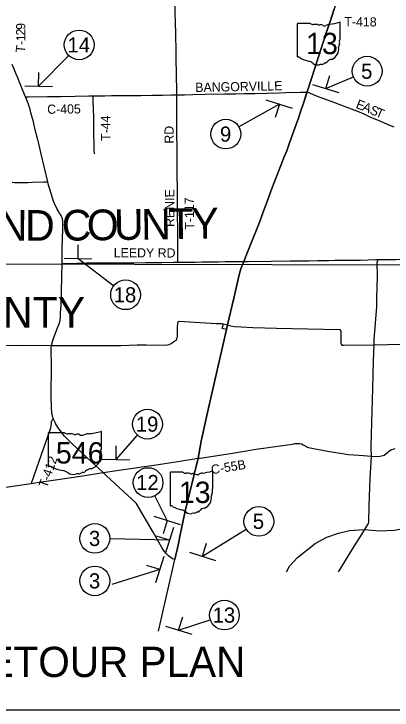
# Model space of a CAD drawing. Extents: x 40529 to 41139, y 15164 to 15584.
# Drawn here: x 40618.2 to 40688.2, y 15164.3 to 15293.1 of the extents above; entities that cross this region are included whole.
import ezdxf

# ---------------------------------------------------------------- set-up
doc = ezdxf.new("R2010")
doc.units = 0
for name, color, linetype in [('Default', 7, 'Continuous'), ('GM_X_County_Road', 7, 'Continuous'), ('GM_X_County_Road_Text', 7, 'Continuous'), ('GM_X_County_Text', 7, 'Continuous'), ('GM_X_Rail_Line', 7, 'Continuous'), ('GM_X_State_Location', 7, 'Continuous'), ('GM_X_State_Route', 7, 'Continuous'), ('GM_X_State_Shield', 7, 'Continuous'), ('GM_X_Township_Road', 7, 'Continuous'), ('GM_X_Township_Road_Text', 7, 'Continuous'), ('SC_Scratch1', 7, 'Continuous'), ('SH_Cut_Line', 7, 'Continuous'), ('SH_Data', 7, 'Continuous'), ('SH_Text', 7, 'Continuous')]:
    doc.layers.add(name, color=color, linetype=linetype)

msp = doc.modelspace()

# ---------------------------------------------------------------- linework, layer by layer
at = {"layer": 'Default'}
for p, q in [((40622.79, 15279.77), (40622.83, 15282.32)), ((40675.89, 15279.34), (40676.65, 15281.77)), ((40620.24, 15279.81), (40625.34, 15279.73)), ((40673.46, 15280.1), (40678.32, 15278.58)), ((40669.76, 15275.65), (40664.9, 15277.18)), ((40667.33, 15276.42), (40666.57, 15273.98)), ((40630.09, 15247.89), (40630.13, 15250.44)), ((40627.54, 15247.93), (40632.64, 15247.85)), ((40637.12, 15210.69), (40637.16, 15213.23)), ((40634.57, 15210.73), (40639.67, 15210.64)), ((40649.03, 15198.61), (40644.17, 15200.13)), ((40646.6, 15199.37), (40645.84, 15196.94)), ((40646.27, 15193.32), (40647.8, 15198.18)), ((40647.03, 15195.75), (40644.6, 15196.51)), ((40653.11, 15192.78), (40653.87, 15195.21)), ((40650.68, 15193.54), (40655.54, 15192.02)), ((40644.47, 15187.91), (40646, 15192.77)), ((40645.23, 15190.34), (40642.8, 15191.1)), ((40648.67, 15179.11), (40649.44, 15181.54)), ((40646.24, 15179.87), (40651.11, 15178.34))]:
    msp.add_line(p, q, dxfattribs=at)
at = {"layer": 'GM_X_County_Road'}
for points in [[(40648.34, 15278.15), (40648.5, 15278.15), (40649.8, 15278.2), (40651.29, 15278.24), (40653.62, 15278.29), (40657.16, 15278.33), (40659.2, 15278.37), (40660.88, 15278.39), (40662, 15278.43), (40662.83, 15278.45), (40667.3, 15278.55), (40668.51, 15278.59), (40671.21, 15278.67), (40672.24, 15278.69), (40672.42, 15278.68)], [(40672.42, 15278.68), (40672.51, 15278.67), (40672.6, 15278.65), (40672.77, 15278.59), (40673.72, 15278.2), (40674.83, 15277.76), (40677.01, 15276.93), (40681.1, 15275.37), (40682.06, 15275), (40682.91, 15274.63), (40684.19, 15274.07), (40685.57, 15273.49), (40687.71, 15272.58), (40688.49, 15272.27)], [(40620.37, 15277.82), (40620.56, 15277.82), (40620.84, 15277.83), (40624.44, 15277.87), (40625.82, 15277.86), (40626.94, 15277.86), (40629.55, 15277.9), (40632.06, 15277.96), (40632.81, 15277.97), (40632.92, 15277.98)], [(40632.92, 15277.98), (40635.04, 15278.01), (40636.25, 15278.02), (40638.29, 15278.05), (40641.72, 15278.07), (40643.85, 15278.11), (40645.71, 15278.13), (40647.39, 15278.15), (40648.34, 15278.15)], [(40661.25, 15212.3), (40662.59, 15212.51), (40665.65, 15212.98), (40669.74, 15213.54), (40670.2, 15213.64), (40670.73, 15213.67), (40671.12, 15213.65), (40671.42, 15213.56), (40671.69, 15213.43), (40672.2, 15213.16), (40672.42, 15213.04), (40672.73, 15212.9), (40673.02, 15212.83), (40673.61, 15212.7), (40676.98, 15212.1), (40678.65, 15211.83), (40679.29, 15211.73), (40680.02, 15211.64), (40681.12, 15211.52), (40682.89, 15211.41), (40684.38, 15211.33), (40685.64, 15211.24), (40686.22, 15211.34), (40686.71, 15211.49), (40687.35, 15212.02), (40687.67, 15212.27), (40687.94, 15212.45), (40688.76, 15212.74)], [(40652.31, 15210.93), (40652.65, 15210.95), (40653.09, 15210.99), (40658.63, 15211.87), (40661.25, 15212.3)]]:
    msp.add_lwpolyline(points, dxfattribs=at)
at = {"layer": 'GM_X_Rail_Line'}
msp.add_lwpolyline([(40668.64, 15189.89), (40669.2, 15190.96), (40670.65, 15192.58), (40673.94, 15195.16), (40676.07, 15196.33), (40678.25, 15197.05), (40680.29, 15197.55), (40682.99, 15197.72), (40685.84, 15197.5), (40688.61, 15197.62), (40690.98, 15198.06), (40693.48, 15198.84), (40697.28, 15200.43), (40705.39, 15204.07), (40707.45, 15205.06), (40708.87, 15205.81), (40710.96, 15207.11), (40717.07, 15211.94), (40723.79, 15217.72), (40727.32, 15220.6), (40729.54, 15222.69), (40732.21, 15225.65), (40737.65, 15232.65)], dxfattribs=at)
at = {"layer": 'GM_X_State_Route'}
msp.add_line((40644.96, 15178.94), (40647.96, 15192.15), dxfattribs=at)
for points in [[(40660.77, 15247.32), (40660.89, 15247.63), (40661.19, 15248.42), (40661.82, 15249.97), (40663.68, 15254.75), (40664.2, 15256.14), (40664.9, 15257.97), (40665.38, 15259.28), (40665.7, 15260.16), (40666.26, 15261.64), (40666.95, 15263.47), (40667.61, 15265.11), (40668.23, 15266.67), (40668.67, 15267.8), (40669.22, 15269.29), (40670.01, 15271.48), (40670.85, 15273.85), (40671.24, 15275), (40671.82, 15276.82), (40672.42, 15278.68), (40672.57, 15279.08), (40674.5, 15285.02), (40675.94, 15289.44), (40676.69, 15291.75), (40677.45, 15294.1)], [(40627.16, 15246.98), (40627.16, 15247.21), (40627.18, 15249.8), (40627.26, 15253.34), (40627.28, 15254.38), (40627.27, 15254.66), (40627.26, 15254.86), (40627.24, 15255.04), (40627.2, 15255.24), (40627.14, 15255.44), (40627.05, 15255.65), (40626.95, 15255.83), (40626.67, 15256.28), (40626.41, 15256.71), (40626.23, 15257.04), (40626.15, 15257.2), (40625.94, 15257.62), (40625.75, 15258.04), (40625.57, 15258.47), (40625.43, 15258.89), (40624.93, 15260.51), (40624.63, 15261.48), (40624.5, 15262), (40624.48, 15262.09), (40623.81, 15264.92), (40623.23, 15267.47), (40622.82, 15269.18), (40622.7, 15269.64), (40622.66, 15269.81), (40622.6, 15270.07), (40622.18, 15271.72), (40621.83, 15273.16), (40621.38, 15274.87), (40621.22, 15275.49), (40620.99, 15276.2), (40620.84, 15276.64), (40620.37, 15277.82), (40619.91, 15278.98), (40619.39, 15280.2), (40618.94, 15281.3), (40618.66, 15282), (40618.27, 15282.93), (40617.93, 15283.79)], [(40625.16, 15221.13), (40625.15, 15221.6), (40625.13, 15222.3), (40625.13, 15222.45), (40625.12, 15222.94), (40625.12, 15223.42), (40625.21, 15227.09), (40625.2, 15228.84), (40625.15, 15230.42), (40625.15, 15231.49), (40625.19, 15231.79), (40625.28, 15232.19), (40625.4, 15232.55), (40625.64, 15233.25), (40626.31, 15235.03), (40626.61, 15235.82), (40626.76, 15236.39), (40626.84, 15237.11), (40626.87, 15237.81), (40626.95, 15239.27), (40627.16, 15246.98)], [(40652.31, 15210.93), (40652.89, 15214.07), (40654.18, 15219.95), (40657.52, 15234.76), (40657.73, 15235.58), (40658.88, 15240.56), (40659.86, 15244.86), (40660.05, 15245.55), (40660.19, 15245.98), (40660.77, 15247.32)], [(40626.57, 15216.35), (40626.38, 15216.64), (40626.13, 15217.01), (40625.93, 15217.35), (40625.84, 15217.53), (40625.71, 15217.79), (40625.56, 15218.13), (40625.45, 15218.44), (40625.36, 15218.79), (40625.3, 15219.08), (40625.27, 15219.28), (40625.24, 15219.45), (40625.22, 15219.68), (40625.2, 15219.95), (40625.18, 15220.24), (40625.19, 15220.44), (40625.17, 15220.91), (40625.16, 15221.13)], [(40645.6, 15194.4), (40643.96, 15197.21), (40640.86, 15202.61), (40635.37, 15207.67), (40634.72, 15208.27), (40632.5, 15210.31), (40629.03, 15213.58), (40627.93, 15214.65), (40627.6, 15215), (40626.98, 15215.79), (40626.65, 15216.22), (40626.57, 15216.35)], [(40649.47, 15199.11), (40649.9, 15201.14), (40652.31, 15210.93)], [(40647.96, 15192.15), (40648.58, 15194.83), (40649.03, 15197.04), (40649.47, 15199.11)], [(40647.96, 15192.15), (40647.57, 15192.3), (40646.82, 15192.85), (40646.37, 15193.28), (40645.89, 15193.91), (40645.6, 15194.4)]]:
    msp.add_lwpolyline(points, dxfattribs=at)
at = {"layer": 'GM_X_State_Shield'}
for p, q in [((40670.64, 15291.28), (40670.64, 15285.28)), ((40673.03, 15291.39), (40670.71, 15291.39)), ((40678.55, 15288.4), (40678.55, 15291.54)), ((40678.55, 15288.4), (40678.55, 15288.4)), ((40624.57, 15215.52), (40624.57, 15209.51)), ((40627.56, 15215.62), (40624.67, 15215.62)), ((40634.46, 15212.63), (40634.46, 15215.77)), ((40634.45, 15212.63), (40634.46, 15212.63)), ((40647.11, 15208.22), (40647.11, 15202.21)), ((40649.5, 15208.32), (40647.19, 15208.32)), ((40655.02, 15205.33), (40655.02, 15208.47)), ((40655.02, 15205.33), (40655.02, 15205.33))]:
    msp.add_line(p, q, dxfattribs=at)
for centre, radius, start, end in [((40670.73, 15291.3), 0.0916, 98.1301, 188.1301), ((40673.58, 15292.08), 0.889, 231.6195, 271.1119), ((40673.88, 15288.02), 3.19, 80.4867, 94.9883), ((40676.8, 15289.55), 1.69, 97.3462, 120.7689), ((40675.73, 15299.57), 8.39, 275.8445, 288.9065), ((40678.46, 15291.55), 0.0881, 351.8621, 97.738), ((40674.6, 15291.33), 0.256, 219.7921, 297.1024), ((40674.98, 15290.63), 0.533, 54.4667, 119.1411), ((40675.67, 15291.59), 0.641, 233.8562, 294.8282), ((40678.86, 15287.08), 0.595, 136.8065, 186.9296), ((40678.53, 15288.16), 0.136, 107.944, 210.337), ((40677.66, 15287.77), 0.818, 340.033, 23.6496), ((40678.45, 15288.38), 0.0942, 289.6038, 7.7341), ((40676.2, 15286.68), 2.1, 292.3089, 8.9858), ((40670.73, 15285.27), 0.0925, 171.9584, 258.3066), ((40670.74, 15285.88), 0.706, 267.339, 280.6039), ((40670.89, 15284.93), 0.254, 29.7484, 93.2717), ((40674.1, 15290.33), 6.06, 240.4129, 257.1985), ((40672.29, 15282.58), 1.9, 47.1842, 75.836), ((40674.34, 15284.9), 1.2, 230.7004, 286.2918), ((40675.04, 15282.83), 0.988, 85.6951, 111.2099), ((40675.13, 15284.45), 0.641, 268.777, 315.5493), ((40675.7, 15283.87), 0.18, 65.7517, 132.6484), ((40675.63, 15284.7), 0.678, 282.8732, 323.2771), ((40677.08, 15283.59), 1.15, 94.4031, 142.5768), ((40647.2, 15208.23), 0.0916, 98.1301, 188.1301), ((40650.06, 15209.02), 0.889, 231.6195, 271.1119), ((40650.35, 15204.95), 3.19, 80.4867, 94.9883), ((40651.08, 15208.26), 0.256, 219.7921, 297.1024), ((40651.45, 15207.57), 0.533, 54.4667, 119.1411), ((40652.14, 15208.52), 0.641, 233.8562, 294.8282), ((40653.27, 15206.49), 1.69, 97.3462, 120.7689), ((40652.2, 15216.51), 8.39, 275.8445, 288.9065), ((40654.93, 15208.48), 0.0881, 351.8621, 97.738), ((40655, 15205.1), 0.136, 107.944, 210.337), ((40654.13, 15204.7), 0.818, 340.033, 23.6496), ((40654.93, 15205.32), 0.0942, 289.6038, 7.7341), ((40652.67, 15203.62), 2.1, 292.3089, 8.9858), ((40655.34, 15204.02), 0.595, 136.8065, 186.9296), ((40647.2, 15202.2), 0.0925, 171.9584, 258.3066), ((40647.22, 15202.82), 0.706, 267.339, 280.6039), ((40647.36, 15201.87), 0.254, 29.7484, 93.2717), ((40650.57, 15207.26), 6.06, 240.4129, 257.1985), ((40648.77, 15199.52), 1.9, 47.1842, 75.836), ((40652.1, 15201.63), 0.678, 282.8732, 323.2771), ((40653.56, 15200.53), 1.15, 94.4031, 142.5768), ((40650.82, 15201.84), 1.2, 230.7004, 286.2918), ((40651.51, 15199.76), 0.988, 85.6951, 111.2099), ((40651.6, 15201.39), 0.641, 268.777, 315.5493), ((40652.18, 15200.81), 0.18, 65.7517, 132.6484)]:
    msp.add_arc(centre, radius, start, end, dxfattribs=at)
for centre, major_axis, start_param, end_param in [((40624.68, 15215.53), (0.115, 0), 1.712693, 3.28349), ((40628.25, 15216.32), (1.11, 0), 4.042523, 4.731795), ((40628.62, 15212.25), (3.99, 0), 1.404758, 1.657858), ((40629.52, 15215.56), (0.321, 0), 3.836095, 5.185415), ((40630, 15214.87), (0.666, 0), 0.950623, 2.079405), ((40630.86, 15215.82), (0.802, 0), 4.081561, 5.145723), ((40632.27, 15213.79), (2.11, 0), 1.699011, 2.107814), ((40630.93, 15223.81), (10.49, 0), 4.814394, 5.042369), ((40634.35, 15215.78), (0.11, 0), 6.141152, 7.989035), ((40634.34, 15212.62), (0.118, 0), 5.05454, 6.418171), ((40634.85, 15211.32), (0.744, 0), 2.387724, 3.262537), ((40634.43, 15212.4), (0.17, 0), 1.883978, 3.671073), ((40633.35, 15212), (1.02, 0), 5.934695, 6.695948), ((40631.52, 15210.92), (2.62, 0), 5.101752, 6.440018), ((40624.68, 15209.5), (0.116, 0), 3.00124, 4.508301), ((40624.7, 15210.12), (0.882, 0), 4.665946, 4.897461), ((40624.88, 15209.17), (0.318, 0), 0.519207, 1.627899), ((40628.9, 15214.56), (7.57, 0), 4.195997, 4.488961), ((40632.63, 15207.83), (1.44, 0), 1.647645, 2.488434), ((40626.64, 15206.82), (2.37, 0), 0.823519, 1.323587), ((40629.2, 15209.14), (1.5, 0), 4.026481, 4.996735), ((40630.07, 15207.06), (1.24, 0), 1.495662, 1.94098), ((40630.18, 15208.69), (0.801, 0), 4.691044, 5.507374), ((40630.9, 15208.11), (0.226, 0), 1.147584, 2.315152), ((40630.81, 15208.93), (0.847, 0), 4.937069, 5.64225)]:
    msp.add_ellipse(centre, major_axis=major_axis, ratio=0.8, start_param=start_param, end_param=end_param, dxfattribs=at)
at = {"layer": 'GM_X_Township_Road'}
for p, q in [((40656.77, 15234.92), (40656.97, 15235.8)), ((40657.52, 15234.76), (40656.77, 15234.92)), ((40648.52, 15210.32), (40652.31, 15210.93))]:
    msp.add_line(p, q, dxfattribs=at)
for points in [[(40648.34, 15278.15), (40648.33, 15279.06), (40648.3, 15281.66), (40648.25, 15285.2), (40648.21, 15286.87), (40648.18, 15288.73), (40648.16, 15289.66), (40648.13, 15291.34), (40648.08, 15293.67), (40648.04, 15295.52), (40647.98, 15298.33), (40647.97, 15300.28), (40647.95, 15302.23), (40647.88, 15305.57), (40647.89, 15306.52), (40647.9, 15307.91), (40647.87, 15308.93), (40647.86, 15310.14), (40647.85, 15310.43), (40647.85, 15310.89), (40647.86, 15312.19), (40647.84, 15313.87), (40647.84, 15314.8), (40647.84, 15315.41)], [(40633.2, 15267.26), (40633.15, 15267.34), (40633.13, 15267.43), (40633.1, 15267.8), (40633.08, 15268.27), (40633.06, 15269.75), (40633.04, 15270.22), (40633.02, 15271.14), (40633.01, 15272.07), (40632.99, 15274.4), (40632.98, 15275.23), (40632.95, 15275.97), (40632.92, 15276.62), (40632.92, 15277.36), (40632.92, 15277.83), (40632.92, 15277.98)], [(40648.54, 15247.2), (40648.54, 15247.43), (40648.54, 15248.27), (40648.56, 15250.04), (40648.54, 15252.37), (40648.53, 15252.92), (40648.53, 15253.67), (40648.51, 15255.53), (40648.49, 15257.77), (40648.48, 15258.14), (40648.48, 15258.7), (40648.48, 15259.72), (40648.47, 15260.65), (40648.44, 15263.45), (40648.43, 15264.94), (40648.43, 15266.8), (40648.41, 15268.29), (40648.4, 15268.85), (40648.38, 15270.43), (40648.37, 15271.82), (40648.36, 15272.38), (40648.36, 15273.58), (40648.37, 15274.42), (40648.38, 15276.47), (40648.34, 15278.05), (40648.34, 15278.15)], [(40617.94, 15261.98), (40617.97, 15261.98), (40618.35, 15261.96), (40619.01, 15261.95), (40619.84, 15261.96), (40620.86, 15261.97), (40621.7, 15261.99), (40623.74, 15262.05), (40624.26, 15262.08), (40624.48, 15262.09)], [(40660.77, 15247.32), (40661.59, 15247.32), (40665.77, 15247.37), (40669.3, 15247.43), (40672.75, 15247.48), (40674.42, 15247.5), (40676.47, 15247.53), (40677.59, 15247.55), (40678.23, 15247.56), (40678.95, 15247.57), (40679.86, 15247.57), (40680.66, 15247.59), (40682.33, 15247.6), (40685.08, 15247.67)], [(40684.29, 15213.1), (40684.41, 15217.54), (40684.59, 15223.84), (40684.72, 15228.94), (40684.82, 15231.93), (40684.88, 15232.88), (40685.09, 15235.93), (40685.34, 15239), (40685.36, 15239.72), (40685.37, 15240.52), (40685.47, 15244.6), (40685.42, 15247.21), (40685.51, 15247.5), (40685.74, 15247.69)], [(40685.08, 15247.67), (40685.49, 15247.68), (40685.74, 15247.69)], [(40685.74, 15247.69), (40686.33, 15247.69), (40688.94, 15247.7), (40691.17, 15247.73), (40695.36, 15247.83), (40696.01, 15247.84), (40696.2, 15247.85), (40697.31, 15247.84), (40698.71, 15247.87), (40700.57, 15247.9), (40701.88, 15247.92), (40704.11, 15247.96), (40705.42, 15247.99), (40706.62, 15248.01), (40708.95, 15248.07), (40709.04, 15248.07)], [(40627.16, 15246.98), (40627.34, 15246.98), (40627.62, 15246.97), (40628.07, 15246.98), (40631.63, 15247.06), (40633.77, 15247.06), (40636.46, 15247.08), (40637.48, 15247.08), (40638.6, 15247.08), (40639.16, 15247.09), (40640.38, 15247.11), (40642.6, 15247.12), (40644, 15247.14), (40645.02, 15247.16), (40645.3, 15247.17), (40645.58, 15247.17), (40647.72, 15247.18), (40648.54, 15247.2)], [(40648.54, 15247.2), (40648.65, 15247.2), (40649.77, 15247.22), (40649.95, 15247.22), (40650.42, 15247.22), (40651.72, 15247.23), (40653.02, 15247.25), (40653.95, 15247.26), (40656, 15247.28), (40657.31, 15247.3), (40658.52, 15247.32), (40659.91, 15247.33), (40660.75, 15247.32), (40660.77, 15247.32)], [(40648.33, 15232.91), (40648.39, 15233.11), (40648.47, 15233.39), (40648.49, 15234.98), (40648.54, 15236.03), (40648.61, 15236.13)], [(40648.61, 15236.13), (40648.62, 15236.15), (40648.82, 15236.26), (40651.7, 15236.08), (40655.63, 15235.86), (40656.76, 15235.84), (40656.97, 15235.8), (40657.73, 15235.58)], [(40657.73, 15235.58), (40658.09, 15235.48), (40658.37, 15235.4), (40659.03, 15235.3), (40660.25, 15235.25), (40662.39, 15235.1), (40666.82, 15235.02), (40678.39, 15234.76), (40678.57, 15234.72), (40678.64, 15234.65), (40678.7, 15234.45), (40678.69, 15232.24), (40678.75, 15232.01), (40678.87, 15231.87), (40679.18, 15231.82), (40684.82, 15231.93)], [(40625.19, 15231.79), (40626.61, 15231.79), (40630.92, 15231.79), (40638.02, 15231.81), (40641.02, 15231.88), (40642.68, 15231.92), (40646.06, 15231.86), (40646.62, 15231.89), (40646.95, 15231.97), (40647.33, 15232.18), (40648.02, 15232.62), (40648.33, 15232.91)], [(40684.82, 15231.93), (40687.33, 15231.95), (40694.11, 15232.1), (40702.2, 15232.34), (40711.73, 15232.62)], [(40584.24, 15231.84), (40586.47, 15231.86), (40590.24, 15231.86), (40596.86, 15231.81), (40598.4, 15231.81), (40605.68, 15231.86), (40610.27, 15231.79), (40618.87, 15231.82), (40625.19, 15231.79)], [(40625.56, 15218.13), (40625.33, 15217.95), (40625.26, 15217.87), (40625.19, 15217.77), (40625.15, 15217.67), (40625.13, 15217.57), (40625.11, 15217.36), (40625, 15216.62), (40624.91, 15216.27), (40624.79, 15215.9), (40623.27, 15211.58), (40621.4, 15206.26)], [(40678.25, 15189.89), (40678.66, 15190.6), (40680.9, 15194.21), (40682.62, 15196.95), (40683.66, 15198.65), (40683.78, 15198.83), (40683.85, 15199.1), (40683.93, 15202.16), (40684.08, 15207.17), (40684.38, 15211.33), (40684.28, 15212.84), (40684.28, 15212.93), (40684.29, 15213.1)], [(40634.72, 15208.27), (40639.8, 15209.03), (40644.52, 15209.69), (40648.52, 15210.32)], [(40621.4, 15206.26), (40622.93, 15206.49), (40626.35, 15206.97), (40630.99, 15207.69), (40634.72, 15208.27)], [(40608.09, 15204.34), (40609.72, 15204.56), (40613.29, 15205.1), (40617.6, 15205.68), (40621.4, 15206.26)]]:
    msp.add_lwpolyline(points, dxfattribs=at)
at = {"layer": 'SC_Scratch1'}
msp.add_lwpolyline([(40528.65, 15584.31), (41138.65, 15584.31), (41138.65, 15164.31), (40528.65, 15164.31)], close=True, dxfattribs=at)
at = {"layer": 'SH_Cut_Line'}
msp.add_line((40533.65, 15247.13), (40737.65, 15246.6), dxfattribs=at)
at = {"layer": 'SH_Data'}
for p, q in [((40622.79, 15279.77), (40628.37, 15285.45)), ((40675.89, 15279.34), (40681.02, 15281.49)), ((40667.33, 15276.42), (40659.82, 15272.24)), ((40630.09, 15247.89), (40636.69, 15242.84)), ((40637.12, 15210.69), (40641.11, 15215.17)), ((40646.6, 15199.37), (40644.28, 15203.97)), ((40653.11, 15192.78), (40661.19, 15197.79)), ((40647.03, 15195.75), (40635.95, 15196.02)), ((40645.23, 15190.34), (40636.33, 15187.56)), ((40648.67, 15179.11), (40654.54, 15181.03))]:
    msp.add_line(p, q, dxfattribs=at)
msp.add_lwpolyline([(40677.67, 15294.78), (40676.69, 15291.75), (40675.94, 15289.44), (40674.5, 15285.02), (40672.57, 15279.08), (40671.82, 15276.82), (40671.24, 15275), (40670.85, 15273.85), (40670.01, 15271.48), (40669.22, 15269.29), (40668.67, 15267.8), (40668.23, 15266.67), (40667.61, 15265.11), (40666.26, 15261.64), (40665.7, 15260.16), (40664.9, 15257.97), (40664.2, 15256.14), (40663.68, 15254.75), (40661.82, 15249.97), (40661.19, 15248.42), (40660.89, 15247.63), (40660.77, 15247.32), (40660.19, 15245.98), (40659.86, 15244.86), (40658.88, 15240.56), (40657.73, 15235.58), (40657.52, 15234.76), (40654.18, 15219.95), (40652.89, 15214.07), (40652.31, 15210.93), (40649.9, 15201.14), (40649.47, 15199.11), (40649.03, 15197.04), (40648.58, 15194.83), (40647.96, 15192.15)], dxfattribs=at)
at = {"layer": 'SH_Text'}
for centre in [(40630.3, 15287.41), (40683.56, 15282.55), (40657.42, 15270.91), (40638.88, 15241.17), (40642.94, 15217.23), (40643.04, 15206.42), (40663.53, 15199.24), (40633.2, 15196.08), (40633.2, 15188.22), (40657.16, 15181.89)]:
    msp.add_circle(centre, 2.75, dxfattribs=at)

# ---------------------------------------------------------------- texts
at = {"layer": 'GM_X_County_Road_Text'}
for s, height, rotation, p in [('BANGORVILLE', 1.7063, 1.1556, (40651.79, 15278.69)), ('E', 1.71, 338.511, (40681.33, 15275.79)), ('C-405', 1.706, 0.8259, (40624.4, 15274.65)), ('A', 1.71, 336.9298, (40682.51, 15275.33)), ('S', 1.71, 336.6155, (40683.89, 15274.74)), ('T', 1.71, 337.3597, (40684.97, 15274.28)), ('C-55B', 1.706, 9.0837, (40654.83, 15207.95))]:
    msp.add_text(s, height=height, rotation=rotation, dxfattribs=at).set_placement(p)
at = {"layer": 'GM_X_County_Text'}
for s, height, rotation, p in [('N', 5.68, 359.9341, (40615.26, 15251.16)), ('D', 5.68, 0.1141, (40620.3, 15251.16)), ('C', 5.68, 0.548, (40627.1, 15251.18)), ('O', 5.68, 0.8316, (40631.75, 15251.22)), ('U', 5.68, 0.8836, (40636.78, 15251.3)), ('N', 5.68, 0.8847, (40641.81, 15251.37)), ('T', 5.68, 0.8839, (40646.83, 15251.45)), ('Y', 5.68, 0.8847, (40651.08, 15251.52)), ('KNOX COUNTY', 5.6818, 359.9722, (40575.67, 15235.11))]:
    msp.add_text(s, height=height, rotation=rotation, dxfattribs=at).set_placement(p)
at = {"layer": 'GM_X_State_Location'}
for s, p in [('13', (40673.07, 15287.47)), ('546', (40627.4, 15211.7)), ('13', (40649.55, 15204.4))]:
    msp.add_text(s, height=0.00568, rotation=0, dxfattribs=at).set_placement(p)
for s, p in [('s', (40674.5, 15287.88)), ('r', (40674.5, 15287.88)), ('s', (40629.4, 15212.12)), ('r', (40629.4, 15212.12)), ('s', (40650.98, 15204.82)), ('r', (40650.98, 15204.82))]:
    msp.add_text(s, height=0.00568, dxfattribs=at).set_placement(p)
at = {"layer": 'GM_X_State_Shield'}
for s, p in [('13', (40672.25, 15285.7)), ('546', (40625.99, 15209.94)), ('13', (40648.72, 15202.64))]:
    msp.add_text(s, height=3.955, dxfattribs=at).set_placement(p)
at = {"layer": 'GM_X_Township_Road_Text'}
for s, height, rotation, p in [('T-418', 1.706, 359.4505, (40679.34, 15290.87)), ('9', 1.71, 90.9562, (40620.35, 15290.21)), ('2', 1.71, 90.9307, (40620.36, 15289.16)), ('1', 1.71, 90.8223, (40620.38, 15288.1)), ('T', 1.71, 83.7175, (40620.24, 15285.89)), ('-', 1.71, 91.3096, (40620.39, 15287.41)), ('T-44', 1.706, 90.3533, (40636.06, 15269.66)), ('RD', 1.706, 90.4978, (40647.8, 15269.15)), ('RENIE', 1.706, 90.4626, (40647.93, 15253.73)), ('T-117', 1.706, 90.8424, (40651.58, 15253.24)), ('LEEDY RD', 1.706, 359.8207, (40636.7, 15248.1)), ('T-412', 1.706, 70.4971, (40624.35, 15205.31))]:
    msp.add_text(s, height=height, rotation=rotation, dxfattribs=at).set_placement(p)
at = {"layer": 'SH_Text'}
for s, height, p in [('14', 2.8, (40628.15, 15286.01)), ('5', 2.8, (40682.44, 15281.15)), ('9', 2.8, (40656.34, 15269.51)), ('18', 2.8, (40636.69, 15239.77)), ('19', 2.8, (40640.78, 15215.83)), ('12', 2.8, (40640.85, 15205.02)), ('5', 2.8, (40662.41, 15197.84)), ('3', 2.8, (40632.11, 15194.68)), ('3', 2.8, (40632.11, 15186.82)), ('13', 2.8, (40654.98, 15180.49)), ('DETOUR PLAN', 5.6, (40607.77, 15170.43))]:
    msp.add_text(s, height=height, dxfattribs=at).set_placement(p)

doc.saveas('drawing.dxf')
